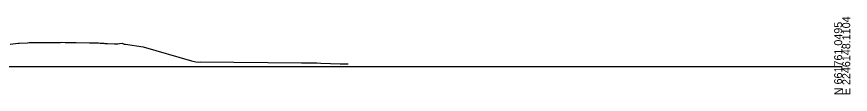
# Model space of a CAD drawing. Extents: x -26 to 603, y -10 to 9526.
# Drawn here: x 311.3 to 602.8, y 1990.3 to 2017.4 of the extents above; entities that cross this region are included whole.
import ezdxf

# ---------------------------------------------------------------- set-up
doc = ezdxf.new("R2010")
doc.units = 0
doc.layers.add('Exist Cross Section Cell', color=7, linetype='Continuous')
doc.layers.add('Exist XS Ground Line', color=7, linetype='Continuous')

msp = doc.modelspace()

# ---------------------------------------------------------------- linework, layer by layer
at = {"layer": 'Exist Cross Section Cell'}
msp.add_line((300, 2000), (600, 2000), dxfattribs=at)
at = {"layer": 'Exist XS Ground Line'}
for p, q in [((308.95, 2007.84), (311.78, 2008.1)), ((311.78, 2008.1), (312.17, 2008.13)), ((312.17, 2008.13), (315.06, 2008.31)), ((315.06, 2008.31), (315.59, 2008.33)), ((315.59, 2008.33), (316.95, 2008.32)), ((316.95, 2008.32), (319, 2008.34)), ((319, 2008.34), (321.08, 2008.36)), ((321.08, 2008.36), (322.77, 2008.38)), ((322.77, 2008.38), (326.56, 2008.4)), ((326.56, 2008.4), (327, 2008.53)), ((327, 2008.53), (328.17, 2008.43)), ((328.17, 2008.43), (328.8, 2008.4)), ((328.8, 2008.4), (330.33, 2008.37)), ((330.33, 2008.37), (332.06, 2008.35)), ((332.06, 2008.35), (336.68, 2008.29)), ((336.68, 2008.29), (337.77, 2008.26)), ((337.77, 2008.26), (339.15, 2008.23)), ((339.15, 2008.23), (339.47, 2008.22)), ((339.47, 2008.22), (339.91, 2008.22)), ((339.91, 2008.22), (340.51, 2008.19)), ((340.51, 2008.19), (341.17, 2008.19)), ((341.17, 2008.19), (341.71, 2008.09)), ((341.71, 2008.09), (342.13, 2008.07)), ((342.13, 2008.07), (343.04, 2008.03)), ((343.04, 2008.03), (345.43, 2007.94)), ((345.43, 2007.94), (346.7, 2007.9)), ((346.7, 2007.9), (347.25, 2007.99)), ((347.25, 2007.99), (348.17, 2008.11)), ((348.17, 2008.11), (348.85, 2007.84)), ((348.85, 2007.84), (349.38, 2007.76)), ((349.38, 2007.76), (355.49, 2006.92)), ((355.49, 2006.92), (372.43, 2001.99)), ((372.43, 2001.99), (373.92, 2001.58)), ((373.92, 2001.58), (374.7, 2001.57)), ((374.7, 2001.57), (375.42, 2001.59)), ((375.42, 2001.59), (410.91, 2001.34)), ((410.91, 2001.34), (416.29, 2001.28)), ((416.29, 2001.28), (417.7, 2001.15)), ((417.7, 2001.15), (424.44, 2000.96)), ((424.44, 2000.96), (427.23, 2000.97))]:
    msp.add_line(p, q, dxfattribs=at)

# ---------------------------------------------------------------- texts
at = {"layer": 'Exist Cross Section Cell'}
for s, p in [('N 661761.0495', (600, 1990)), ('E 2246148.1104', (602.8, 1990))]:
    msp.add_text(s, height=2.8, rotation=90, dxfattribs=at).set_placement(p)

doc.saveas('drawing.dxf')
